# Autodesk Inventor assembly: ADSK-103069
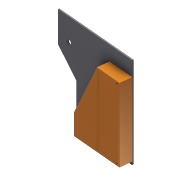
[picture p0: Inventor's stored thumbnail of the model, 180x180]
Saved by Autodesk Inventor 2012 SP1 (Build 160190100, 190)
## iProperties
Shininess: 20.0
Created: 2001-03
Part Number: ADSK-103069
Document SubType Name: Assembly
Designer: Administrator
Stock Number: ADSK-103069
Density: 0.0
Volumn: 0.0
Area: 0.0
PropertySet Name: Model Information
Control State: 0
Master: False
Checked Out: False
Author: Administrator
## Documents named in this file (6)
- D:\AOTC\Autodesk Inventor 2012 Essential for New Users\Autodesk Inventor 2012 Essentials - Project Files\Learning\Workspace\Sub-Assemblies\ADSK-103069.iam
- D:\AOTC\Autodesk Inventor 2012 Essential for New Users\Autodesk Inventor 2012 Essentials - Project Files\Learning\Workspace\Parts\ADSK-103493.ipt
- D:\AOTC\Autodesk Inventor 2012 Essential for New Users\Autodesk Inventor 2012 Essentials - Project Files\Learning\Workspace\Parts\ADSK-103494.ipt
- D:\AOTC\Autodesk Inventor 2012 Essential for New Users\Autodesk Inventor 2012 Essentials - Project Files\Learning\Workspace\Parts\ADSK-103496.ipt
- D:\AOTC\Autodesk Inventor 2012 Essential for New Users\Autodesk Inventor 2012 Essentials - Project Files\Learning\Workspace\Parts\ADSK-103495.ipt
- D:\AOTC\Autodesk Inventor 2012 Essential for New Users\Autodesk Inventor 2012 Essentials - Project Files\Learning\Workspace\Parts\ADSK-103945.ipt
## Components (6 placed, 5 different names)
1. ADSK-103493:1 — Flush:1, Mate:1, Flush:2, Flush:3, Mate:2, Mate:3, Mate:4, Mate:5
2. ADSK-103494:1 — Flush:1, Insert:1, Insert:2, Mate:2, Mate:3, Mate:6
3. ADSK-103496:1 — Insert:1
4. ADSK-103496:3 — Insert:2
5. ADSK-103495:2 — Mate:4, Mate:5, Mate:6
6. ADSK-103945:1 — Mate:1, Flush:2, Flush:3
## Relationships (11: Mate 6, Flush 3, Insert 2)
- Flush:1: ADSK-103493:1 ↔ ADSK-103494:1
- Insert:1: ADSK-103494:1 ↔ ADSK-103496:1
- Insert:2: ADSK-103494:1 ↔ ADSK-103496:3
- Mate:1: ADSK-103493:1 ↔ ADSK-103945:1
- Flush:2: ADSK-103493:1 ↔ ADSK-103945:1
- Flush:3: ADSK-103493:1 ↔ ADSK-103945:1
- Mate:2: ADSK-103493:1 ↔ ADSK-103494:1
- Mate:3: ADSK-103493:1 ↔ ADSK-103494:1
- Mate:4: ADSK-103493:1 ↔ ADSK-103495:2
- Mate:5: ADSK-103493:1 ↔ ADSK-103495:2
- Mate:6: ADSK-103494:1 ↔ ADSK-103495:2
